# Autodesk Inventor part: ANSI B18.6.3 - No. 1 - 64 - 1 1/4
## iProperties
Comments: To add or edit properties for Autodesk Inventor files, use iProperties.
Created: 2004-12
Part Number: ANSI B18.6.3 - No. 1 - 64 - 1 1/4
Vendor: Autodesk Inc.
Document SubType Name: Modeling
Designer: John Blackburn
Material: Default
Description: Plain Hex Head Machine Screw
Standard: ANSI B18.6.3
Alert: To add or edit properties for Autodesk Inventor files, use iProperties.
Control State: 0
Master: False
Checked Out: False
Shininess: 64.0
Length Units: 11272
Angle Units: 11279
Time Units: 11290
Mass Units: 11286
Length Display Precision: 3
Angle Display Precision: 2
Compacted: True
EGR: 3
Classification: un/spsc 31161513
Density: 0.0
Volumn: 0.0
Area: 0.0
PropertySet Name: Model Information
Author: John Blackburn
Revision Number: 8
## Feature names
1. Body [Revolution]
2. Head [Extrusion]
3. Chamfer1 [Revolution]
4. Chamfer2
